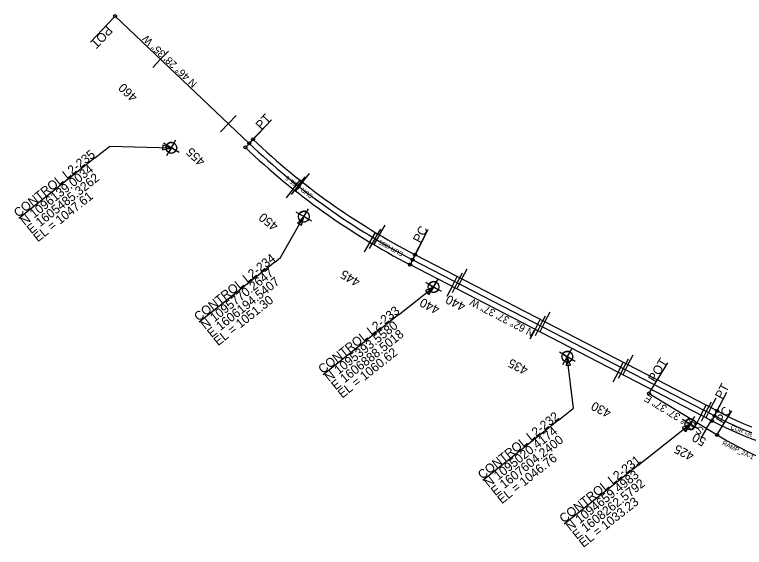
# Model space of a CAD drawing. Extents: x 1603447 to 1622636, y 1083818 to 1103958.
# Drawn here: x 1604646 to 1608552, y 1094000 to 1096852 of the extents above; entities that cross this region are included whole.
import ezdxf

# ---------------------------------------------------------------- set-up
doc = ezdxf.new("R2010")
doc.units = 0
for name, color, linetype in [('Level 1', 7, 'Continuous'), ('RD_HC_Points', 7, 'Continuous'), ('RD_HC_SUR_Bearing_TX400', 7, 'Continuous'), ('RD_HC_SUR_CL400', 7, 'Continuous'), ('RD_HC_SUR_PC_PT_400', 7, 'Continuous'), ('RD_HC_SUR_Tic400', 7, 'Continuous'), ('RD_HC_SUR_TX_Sta400', 7, 'Continuous'), ('RD_SHT_Misc1', 7, 'Continuous'), ('RD_TX_Misc1', 7, 'Continuous')]:
    doc.layers.add(name, color=color, linetype=linetype)

msp = doc.modelspace()

# ---------------------------------------------------------------- linework, layer by layer
at = {"layer": 'RD_HC_Points'}
for p, q in [((1605073.7, 1096082.8), (1604668.6, 1095760.7)), ((1606038.9, 1095527.3), (1605633.4, 1095204.8)), ((1606702.8, 1095246.3), (1606297.8, 1094924.1)), ((1607556.8, 1094680.7), (1607151.8, 1094358.4)), ((1607981.9, 1094437.9), (1607588.1, 1094124.7))]:
    msp.add_line(p, q, dxfattribs=at)
for points in [[(1605073.7, 1096082.8), (1605156.2, 1096148.5), (1605485.3, 1096139)], [(1606038.9, 1095527.3), (1606068.9, 1095551.2), (1606194.5, 1095770.3)], [(1606702.8, 1095246.3), (1606708.6, 1095250.9), (1606888.5, 1095393.6)], [(1607556.8, 1094680.7), (1607637.5, 1094744.8), (1607604.2, 1095020.4)], [(1607981.9, 1094437.9), (1608223.3, 1094629.9), (1608262.6, 1094659.5)]]:
    msp.add_lwpolyline(points, dxfattribs=at)
for points in [[(1605438.6, 1096127.9), (1605485.3, 1096139), (1605439.3, 1096152.8)], [(1606182.3, 1095723.9), (1606194.5, 1095770.3), (1606160.7, 1095736.2)], [(1606859.9, 1095355), (1606888.5, 1095393.6), (1606844.5, 1095374.5)], [(1607622.1, 1094975.9), (1607604.2, 1095020.4), (1607597.5, 1094972.9)], [(1608233, 1094621.7), (1608262.6, 1094659.5), (1608218.1, 1094641.5)]]:
    msp.add_lwpolyline(points, close=True, dxfattribs=at)
at = {"layer": 'RD_HC_SUR_CL400'}
for p, q in [((1605902, 1096162.3), (1605184.2, 1096844.1)), ((1608405.8, 1094730), (1606790, 1095566.6)), ((1608391.9, 1094703.4), (1606776.2, 1095540)), ((1608378.1, 1094676.8), (1606762.4, 1095513.3)), ((1608042.1, 1094823.7), (1608405.7, 1094602.1))]:
    msp.add_line(p, q, dxfattribs=at)
for centre, radius, start, end in [((1608532.4, 1098932), 3789.7, 226.4765, 242.6268), ((1608532.4, 1098932), 3819.7, 226.4765, 242.6268), ((1608532.4, 1098932), 3849.7, 226.4765, 242.6268), ((1609270, 1096399.4), 1909.9, 242.6268, 261.5065), ((1609289.4, 1096392.5), 1882.8, 242.0082, 260.8939), ((1609270, 1096399.4), 1939.9, 242.6268, 261.5065), ((1609446.9, 1096309.6), 2000, 238.6268, 252.8371)]:
    msp.add_arc(centre, radius, start, end, dxfattribs=at)
at = {"layer": 'RD_HC_SUR_PC_PT_400'}
for p, q in [((1605178.7, 1096838.2), (1605052.4, 1096705.3)), ((1605907.5, 1096168.2), (1606001, 1096266.6)), ((1605928.2, 1096189.9), (1606021.7, 1096288.4)), ((1605886.8, 1096146.4), (1605980.4, 1096244.9)), ((1606779.9, 1095547.1), (1606846, 1095674.7)), ((1606793.7, 1095573.7), (1606859.8, 1095701.4)), ((1606766.1, 1095520.4), (1606832.2, 1095648.1)), ((1608046.3, 1094830.5), (1608141.8, 1094987.1)), ((1608395.6, 1094710.5), (1608458, 1094831.2)), ((1608381.8, 1094683.9), (1608444.3, 1094804.5)), ((1608409.8, 1094608.9), (1608484.7, 1094731.6))]:
    msp.add_line(p, q, dxfattribs=at)
for centre in [(1605184.2, 1096844.1), (1605922.6, 1096184.1), (1605881.3, 1096140.6), (1605902, 1096162.3), (1606790, 1095566.6), (1606762.4, 1095513.3), (1606776.2, 1095540), (1608042.1, 1094823.7), (1608405.8, 1094730), (1608391.9, 1094703.4), (1608378.1, 1094676.8), (1608405.7, 1094602.1)]:
    msp.add_circle(centre, 8, dxfattribs=at)
at = {"layer": 'RD_HC_SUR_Tic400'}
for p, q in [((1605210.3, 1096819.3), (1605210.3, 1096819.3)), ((1605282.8, 1096750.4), (1605282.8, 1096750.4)), ((1605355.3, 1096681.5), (1605355.3, 1096681.5)), ((1605427.8, 1096612.7), (1605469.2, 1096656.2)), ((1605427.8, 1096612.7), (1605386.5, 1096569.2)), ((1605500.4, 1096543.8), (1605500.4, 1096543.8)), ((1605572.9, 1096474.9), (1605572.9, 1096474.9)), ((1605645.4, 1096406.1), (1605645.4, 1096406.1)), ((1605717.9, 1096337.2), (1605717.9, 1096337.2)), ((1605790.4, 1096268.3), (1605831.7, 1096311.8)), ((1605790.4, 1096268.3), (1605749.1, 1096224.8)), ((1605862.9, 1096199.5), (1605862.9, 1096199.5)), ((1605959.4, 1096149.6), (1605959.4, 1096149.6)), ((1605909.5, 1096114.1), (1605909.5, 1096114.1)), ((1605935.6, 1096130.8), (1605935.6, 1096130.8)), ((1606009.8, 1096063.8), (1606009.8, 1096063.8)), ((1606033.7, 1096082.7), (1606033.7, 1096082.7)), ((1605983.6, 1096046.9), (1605983.6, 1096046.9)), ((1606085.8, 1095998.7), (1606085.8, 1095998.7)), ((1606109.8, 1096017.8), (1606109.8, 1096017.8)), ((1606187.5, 1095954.9), (1606224.7, 1096002)), ((1606059.3, 1095981.7), (1606059.3, 1095981.7)), ((1606136.8, 1095918.5), (1606174.1, 1095965.4)), ((1606187.5, 1095954.9), (1606150.4, 1095907.7)), ((1606163.4, 1095935.7), (1606200.6, 1095982.8)), ((1606136.8, 1095918.5), (1606099.5, 1095871.5)), ((1606163.4, 1095935.7), (1606126.2, 1095888.6)), ((1606242.6, 1095874.7), (1606242.6, 1095874.7)), ((1606266.9, 1095894), (1606266.9, 1095894)), ((1606215.9, 1095857.3), (1606215.9, 1095857.3)), ((1606347.8, 1095835.3), (1606347.8, 1095835.3)), ((1606296.5, 1095798.1), (1606296.5, 1095798.1)), ((1606323.4, 1095815.8), (1606323.4, 1095815.8)), ((1606405.8, 1095759.1), (1606405.8, 1095759.1)), ((1606430.3, 1095778.7), (1606430.3, 1095778.7)), ((1606378.7, 1095741.1), (1606378.7, 1095741.1)), ((1606514.2, 1095724.4), (1606514.2, 1095724.4)), ((1606599.6, 1095672.3), (1606630.2, 1095723.9)), ((1606462.3, 1095686.3), (1606462.3, 1095686.3)), ((1606489.6, 1095704.5), (1606489.6, 1095704.5)), ((1606547.3, 1095633.6), (1606578.2, 1095685)), ((1606574.7, 1095652.1), (1606605.5, 1095703.6)), ((1606547.3, 1095633.6), (1606516.3, 1095582.2)), ((1606574.7, 1095652.1), (1606544, 1095600.6)), ((1606599.6, 1095672.3), (1606569, 1095620.6)), ((1606661.3, 1095602), (1606661.3, 1095602)), ((1606686.2, 1095622.4), (1606686.2, 1095622.4)), ((1606633.6, 1095583.1), (1606633.6, 1095583.1)), ((1606774.2, 1095574.8), (1606774.2, 1095574.8)), ((1606721.2, 1095535), (1606721.2, 1095535)), ((1606749.1, 1095554.1), (1606749.1, 1095554.1)), ((1606863, 1095528.8), (1606863, 1095528.8)), ((1606809.9, 1095488.7), (1606809.9, 1095488.7)), ((1606837.8, 1095508.1), (1606837.8, 1095508.1)), ((1606951.8, 1095482.8), (1606951.8, 1095482.8)), ((1607040.6, 1095436.9), (1607068.2, 1095490.1)), ((1606898.7, 1095442.8), (1606898.7, 1095442.8)), ((1606926.6, 1095462.1), (1606926.6, 1095462.1)), ((1606987.5, 1095396.8), (1607015.1, 1095450.1)), ((1607015.4, 1095416.1), (1607043, 1095469.4)), ((1607015.4, 1095416.1), (1606987.8, 1095362.8)), ((1607040.6, 1095436.9), (1607013, 1095383.6)), ((1606987.5, 1095396.8), (1606959.9, 1095343.5)), ((1607104.2, 1095370.1), (1607104.2, 1095370.1)), ((1607129.4, 1095390.9), (1607129.4, 1095390.9)), ((1607076.3, 1095350.8), (1607076.3, 1095350.8)), ((1607193, 1095324.1), (1607193, 1095324.1)), ((1607218.2, 1095344.9), (1607218.2, 1095344.9)), ((1607165.1, 1095304.8), (1607165.1, 1095304.8)), ((1607307, 1095298.9), (1607307, 1095298.9)), ((1607253.9, 1095258.8), (1607253.9, 1095258.8)), ((1607281.8, 1095278.2), (1607281.8, 1095278.2)), ((1607395.8, 1095252.9), (1607395.8, 1095252.9)), ((1607484.6, 1095207), (1607512.2, 1095260.2)), ((1607342.7, 1095212.9), (1607342.7, 1095212.9)), ((1607370.6, 1095232.2), (1607370.6, 1095232.2)), ((1607431.5, 1095166.9), (1607459.1, 1095220.2)), ((1607484.6, 1095207), (1607457, 1095153.7)), ((1607459.5, 1095186.2), (1607487, 1095239.5)), ((1607431.5, 1095166.9), (1607403.9, 1095113.6)), ((1607459.5, 1095186.2), (1607431.9, 1095132.9)), ((1607548.3, 1095140.2), (1607548.3, 1095140.2)), ((1607573.4, 1095161), (1607573.4, 1095161)), ((1607520.3, 1095120.9), (1607520.3, 1095120.9)), ((1607637.1, 1095094.3), (1607637.1, 1095094.3)), ((1607662.2, 1095115), (1607662.2, 1095115)), ((1607609.1, 1095074.9), (1607609.1, 1095074.9)), ((1607725.9, 1095048.3), (1607725.9, 1095048.3)), ((1607751, 1095069), (1607751, 1095069)), ((1607697.9, 1095028.9), (1607697.9, 1095028.9)), ((1607839.8, 1095023.1), (1607839.8, 1095023.1)), ((1607903.5, 1094956.3), (1607931.1, 1095009.6)), ((1607928.6, 1094977.1), (1607956.2, 1095030.4)), ((1607786.7, 1094983), (1607786.7, 1094983)), ((1607814.7, 1095002.3), (1607814.7, 1095002.3)), ((1607875.5, 1094937), (1607903.1, 1094990.3)), ((1607928.6, 1094977.1), (1607901, 1094923.8)), ((1607875.5, 1094937), (1607848, 1094883.7)), ((1607903.5, 1094956.3), (1607875.9, 1094903)), ((1608017.4, 1094931.1), (1608017.4, 1094931.1)), ((1607992.3, 1094910.3), (1607992.3, 1094910.3)), ((1607964.4, 1094891), (1607964.4, 1094891)), ((1608081.1, 1094864.4), (1608081.1, 1094864.4)), ((1608106.2, 1094885.1), (1608106.2, 1094885.1)), ((1608053.2, 1094845), (1608053.2, 1094845)), ((1608169.9, 1094818.4), (1608169.9, 1094818.4)), ((1608195, 1094839.1), (1608195, 1094839.1)), ((1608093.4, 1094792.4), (1608093.4, 1094792.4)), ((1608142, 1094799.1), (1608142, 1094799.1)), ((1608283.8, 1094793.2), (1608283.8, 1094793.2)), ((1608347.5, 1094726.4), (1608375.1, 1094779.7)), ((1608372.6, 1094747.2), (1608400.2, 1094800.5)), ((1608178.8, 1094740.4), (1608178.8, 1094740.4)), ((1608230.8, 1094753.1), (1608230.8, 1094753.1)), ((1608258.7, 1094772.4), (1608258.7, 1094772.4)), ((1608319.6, 1094707.1), (1608347.2, 1094760.4)), ((1608372.6, 1094747.2), (1608345.1, 1094693.9)), ((1608319.6, 1094707.1), (1608292, 1094653.8)), ((1608347.5, 1094726.4), (1608319.9, 1094673.1)), ((1608461.6, 1094701.5), (1608461.6, 1094701.5)), ((1608264.2, 1094688.3), (1608264.2, 1094688.3)), ((1608349.6, 1094636.3), (1608380.8, 1094687.5)), ((1608408.5, 1094661.4), (1608408.5, 1094661.4)), ((1608436.6, 1094681), (1608436.6, 1094681)), ((1608349.6, 1094636.3), (1608318.3, 1094585)), ((1608499.2, 1094619.3), (1608499.2, 1094619.3)), ((1608527.7, 1094639.8), (1608527.7, 1094639.8)), ((1608435.1, 1094584.4), (1608435.1, 1094584.4)), ((1608522.6, 1094536), (1608522.6, 1094536))]:
    msp.add_line(p, q, dxfattribs=at)
at = {"layer": 'RD_SHT_Misc1'}
for p, q in [((1605460.5, 1096097), (1605510.1, 1096181)), ((1605527.3, 1096114.2), (1605443.4, 1096163.8)), ((1605460.6, 1096153.6), (1605485.3, 1096139)), ((1605485.3, 1096139), (1605499.9, 1096163.8)), ((1605485.3, 1096139), (1605470.7, 1096114.2)), ((1605510.1, 1096124.4), (1605485.3, 1096139)), ((1606236.5, 1095745.5), (1606152.6, 1095795.1)), ((1606169.7, 1095728.3), (1606219.3, 1095812.2)), ((1606194.5, 1095770.3), (1606209.2, 1095795)), ((1606169.8, 1095784.9), (1606194.5, 1095770.3)), ((1606194.5, 1095770.3), (1606179.9, 1095745.5)), ((1606219.3, 1095755.6), (1606194.5, 1095770.3)), ((1606930.5, 1095368.8), (1606846.5, 1095418.4)), ((1606863.7, 1095351.6), (1606913.3, 1095435.5)), ((1606863.7, 1095408.2), (1606888.5, 1095393.6)), ((1606888.5, 1095393.6), (1606903.1, 1095418.3)), ((1606888.5, 1095393.6), (1606873.9, 1095368.8)), ((1606913.3, 1095378.9), (1606888.5, 1095393.6)), ((1607579.4, 1094978.4), (1607629, 1095062.4)), ((1607646.2, 1094995.6), (1607562.3, 1095045.2)), ((1607579.5, 1095035), (1607604.2, 1095020.4)), ((1607604.2, 1095020.4), (1607589.6, 1094995.7)), ((1607604.2, 1095020.4), (1607618.9, 1095045.2)), ((1607629, 1095005.8), (1607604.2, 1095020.4)), ((1608237.8, 1094617.5), (1608287.4, 1094701.5)), ((1608304.6, 1094634.7), (1608220.6, 1094684.3)), ((1608237.8, 1094674.1), (1608262.6, 1094659.5)), ((1608262.6, 1094659.5), (1608248, 1094634.7)), ((1608262.6, 1094659.5), (1608277.2, 1094684.3)), ((1608287.3, 1094644.9), (1608262.6, 1094659.5))]:
    msp.add_line(p, q, dxfattribs=at)
for centre in [(1605485.3, 1096139), (1606194.5, 1095770.3), (1606888.5, 1095393.6), (1607604.2, 1095020.4), (1608262.6, 1094659.5)]:
    msp.add_circle(centre, 28.8, dxfattribs=at)
for centre, start, end in [((1605485.3, 1096139), 59.4326, 149.4326), ((1605485.3, 1096139), 239.4326, 329.4326), ((1606194.5, 1095770.3), 59.4326, 149.4326), ((1606194.5, 1095770.3), 239.4326, 329.4326), ((1606888.5, 1095393.6), 59.4326, 149.4326), ((1606888.5, 1095393.6), 239.4326, 329.4326), ((1607604.2, 1095020.4), 59.4326, 149.4326), ((1607604.2, 1095020.4), 239.4326, 329.4326), ((1608262.6, 1094659.5), 59.4326, 149.4326), ((1608262.6, 1094659.5), 239.4326, 329.4326)]:
    msp.add_arc(centre, 28.8, start, end, dxfattribs=at)

# ---------------------------------------------------------------- texts
at = {"layer": 'Level 1'}
for s, rotation, p in [('455', 136.4765, (1605670.1, 1096070.9)), ('445', 149.1679, (1606500.8, 1095433.1)), ('435', 152.6268, (1607398.8, 1094963.1)), ('425', 152.6268, (1608286.9, 1094503.3))]:
    msp.add_text(s, height=48, rotation=rotation, dxfattribs=at).set_placement(p)
at = {"layer": 'RD_HC_Points'}
for s, p in [('CONTROL L2-235', (1604666.1, 1095763.8)), ('N 1096139.0034', (1604701, 1095720)), ('E 1605485.3262', (1604735.9, 1095676.1)), ('EL = 1047.61', (1604770.7, 1095632.3)), ('CONTROL L2-234', (1605630.9, 1095207.9)), ('N 1095770.2647', (1605665.8, 1095164.1)), ('E 1606194.5407', (1605700.6, 1095120.2)), ('EL = 1051.30', (1605735.5, 1095076.4)), ('CONTROL L2-233', (1606295.3, 1094927.3)), ('N 1095393.5580', (1606330.2, 1094883.4)), ('E 1606888.5018', (1606365, 1094839.6)), ('EL = 1060.62', (1606399.9, 1094795.8)), ('CONTROL L2-232', (1607149.3, 1094361.6)), ('N 1095020.4174', (1607184.1, 1094317.7)), ('E 1607604.2400', (1607219, 1094273.9)), ('EL = 1046.76', (1607253.8, 1094230.1)), ('CONTROL L2-231', (1607585.6, 1094127.8)), ('N 1094659.4983', (1607620.5, 1094084)), ('E 1608262.5792', (1607655.4, 1094040.1)), ('EL = 1033.23', (1607690.2, 1093996.3))]:
    msp.add_text(s, height=48, rotation=38.4995, dxfattribs=at).set_placement(p)
at = {"layer": 'RD_HC_SUR_Bearing_TX400'}
for s, rotation, p in [('N 46%%d 28\' 35" W', 136.4765, (1605626.7, 1096486.1)), ('N 62%%d 37\' 37" W', 152.6268, (1607431.4, 1095160.2)), ('S 58%%d 37\' 37" E', 148.6268, (1608338.5, 1094633.3))]:
    msp.add_text(s, height=40, rotation=rotation, dxfattribs=at).set_placement(p)
at = {"layer": 'RD_HC_SUR_PC_PT_400'}
for s, rotation, p in [('POT', 226.4765, (1605140.9, 1096795.5)), ('PT', 46.4765, (1605966, 1096232.6)), ('PC', 62.6268, (1606818.1, 1095625.3)), ('POT', 58.6268, (1608074.3, 1094880.3)), ('PT', 62.0082, (1608434.5, 1094788.4)), ('PC', 58.6268, (1608437.8, 1094658.6))]:
    msp.add_text(s, height=48, rotation=rotation, dxfattribs=at).set_placement(p)
at = {"layer": 'RD_HC_SUR_TX_Sta400'}
for s, rotation, p in [('460', 136.4765, (1605307.8, 1096415)), ('450', 141.6679, (1606061.7, 1095728)), ('440', 152.6268, (1606925.9, 1095287.3)), ('440', 152.6268, (1607064.5, 1095303.8)), ('430', 152.6268, (1607843.1, 1094733.1)), ('50', 148.6268, (1608352.1, 1094578.2))]:
    msp.add_text(s, height=48, rotation=rotation, dxfattribs=at).set_placement(p)
at = {"layer": 'RD_TX_Misc1'}
for s, rotation, p in [('CUR I385-6', 142.9164, (1606246.1, 1095884.2)), ('CUR I385-7', 150.8833, (1606729.3, 1095576.2)), ('CUR I385-6', 339.8242, (1608475.4, 1094633.9)), ('RAMP_2A-1', 333.8067, (1608430.1, 1094550.5))]:
    msp.add_text(s, height=24, rotation=rotation, dxfattribs=at).set_placement(p)

doc.saveas('drawing.dxf')
